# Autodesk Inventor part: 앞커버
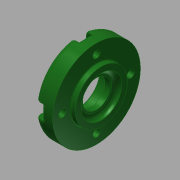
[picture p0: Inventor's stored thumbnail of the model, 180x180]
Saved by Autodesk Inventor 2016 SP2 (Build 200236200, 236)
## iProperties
Created: 2015-11
Part Number: 앞커버
Material: 알루미늄 6061
Document SubType Name: Modeling
Designer: mduedu
Density: 1 g/cm^3
Appearance: 매끄러움 - 짙은 산림 녹색
Author: mduedu
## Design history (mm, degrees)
sketch "스케치1"
  geometry: L1 (-7, 0)-(7, 0); L2 (-7, 0)-(-7, 27); L3 (-7, 27)-(4, 27); L4 (4, 27)-(4, 16); L5 (4, 16)-(7, 16); L6 (7, 16)-(7, 0); 2 further points
  constraints: 12 end point, 3 perpendicular, 2 parallel, 1 coincident, 1 horizontal, 1 midpoint
  dimensions: "d0" = 14 distance of L1.start L1.end; "d1" = 54 diameter of L3 L1; "d2" = 3 distance of L4.end L5.end; "d3" = 32 diameter of L5 L1
revolve "회전1" sketch "스케치1" stored, may be unused: angle "d4" = 90 deg
hole "구멍1" diameter "d7" = 25; stored, may be unused: countersink angle "d11" = 90 deg, drill point angle "d13" = 0 deg; dims "d5" = 10, "d6" = 10, "d8" = 6, "d9" = 4, "d10" = 2, "d12" = 3
hole "구멍2" diameter "d16" = 25; stored, may be unused: countersink angle "d20" = 90 deg, drill point angle "d22" = 0 deg; dims "d17" = 6, "d18" = 4, "d19" = 2, "d21" = 7.7, "d58" = 10, "d59" = 10
hole "구멍3" diameter "d25" = 17; stored, may be unused: countersink angle "d29" = 90 deg, drill point angle "d31" = 0 deg; dims "d23" = 10, "d24" = 10, "d26" = 6, "d27" = 4, "d28" = 2, "d30" = 4.2
chamfer "모따기1" distance "d32" = 0.6; stored, may be unused: second distance "d33" = 2, angle "d34" = 30 deg
fillet "모깎기1" dims "d35" = 0.3
fillet "모깎기2" dims "d36" = 3
fillet "모깎기3" dims "d37" = 3
fillet "모깎기4" dims "d38" = 0.3
sketch "스케치3" dims "d61" = 42
  geometry: C1 r 27 at (0, 0) reference; 2 further points
  constraints: 2 vertical alignment, 1 coincident, 2 other
hole "구멍4" sketch "스케치3" at (0, 21) diameter "d44" = 4.5; stored, may be unused: countersink angle "d48" = 90 deg, drill point angle "d50" = 0 deg; dims "d45" = 6, "d46" = 8, "d47" = 4.6, "d49" = 8
sketch "스케치4"
  geometry: L1 (-4, 5.702)-(-4, 0); L2 (4, 5.702)-(4, 0); A1 r 27 centre (0, -21) between (-4, 5.702) and (4, 5.702) reference; A2 r 4 centre (0, 0) between (-2.824, 2.833) and (2.824, 2.833) reference
  constraints: 4 end point, 4 point on circle, 2 tangent, 2 vertical
extrude "돌출1" cut sketch "스케치4" stored distance "d51" = 0; taper "d52" = 0 deg
fillet "모깎기5" dims "d56" = 0.3
fillet "모깎기6" dims "d57" = 1
node "솔리드1"
pattern_circular "원형 패턴2" dims angle "d64" = 360 deg
pattern_circular "원형 패턴1" dims angle "d54" = 360 deg
